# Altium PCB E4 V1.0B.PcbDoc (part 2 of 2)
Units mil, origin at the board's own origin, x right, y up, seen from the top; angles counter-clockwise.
Board outline 3543.31 x 2637.8 mil, 2 copper layers (Top Layer, Bottom Layer), stack 77.559 mil thick; 151 components, 120 nets, 552 pads, 470 vias.
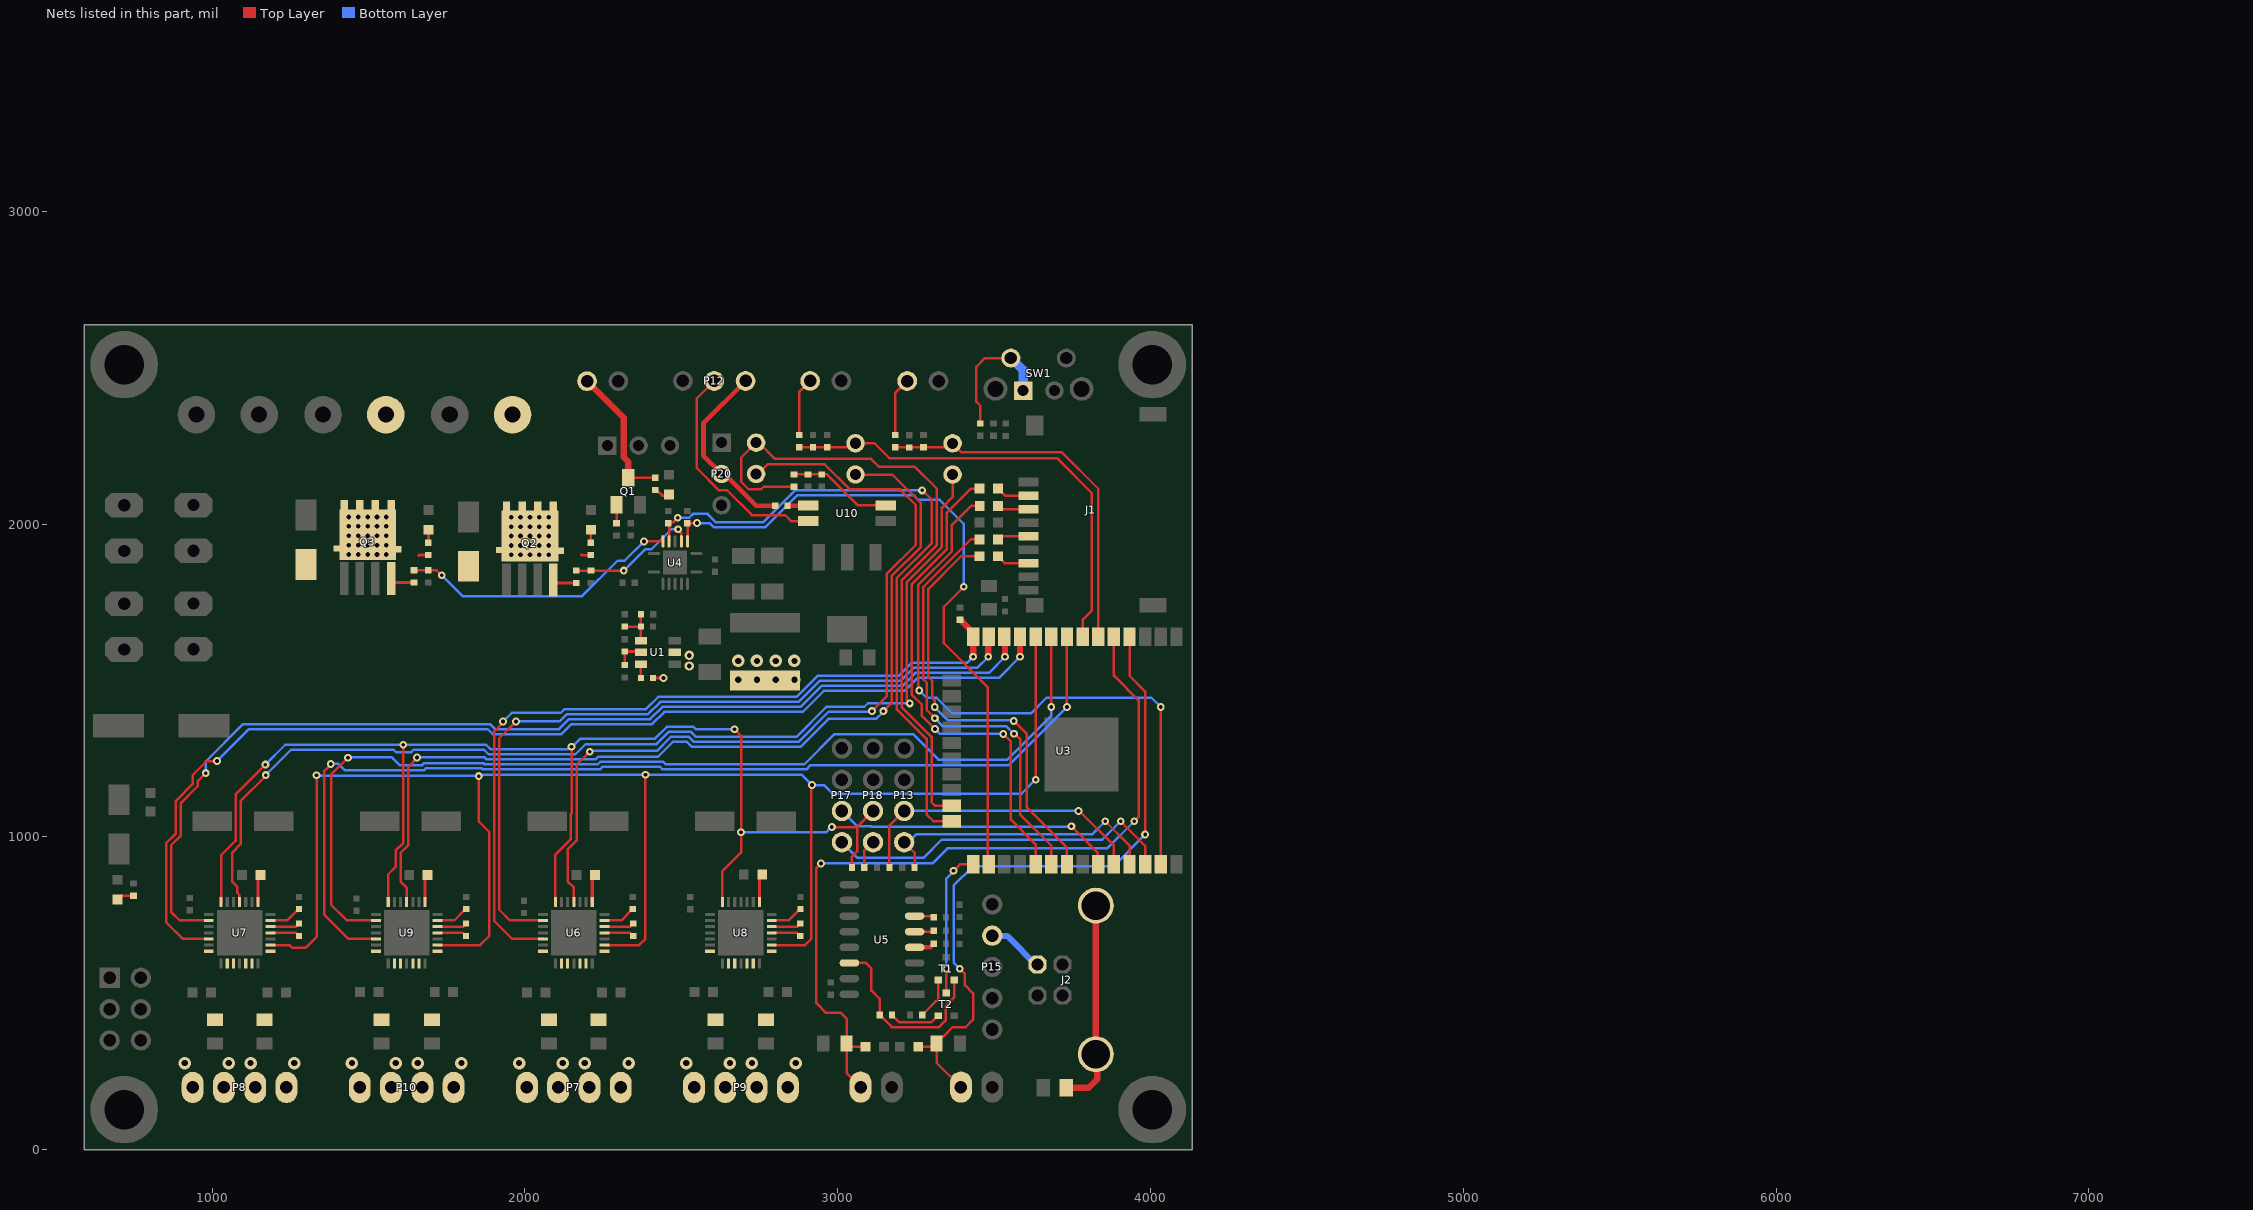
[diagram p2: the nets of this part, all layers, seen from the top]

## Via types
v1: diameter 30, hole 15, Top Layer to Bottom Layer, tented both sides, 177 vias
v2: diameter 40, hole 20, Top Layer to Bottom Layer, tented both sides, 114 vias
v3: diameter 25, hole 12, Top Layer to Bottom Layer, tented both sides, 109 vias
v4: diameter 35, hole 20, Top Layer to Bottom Layer, 36 vias
v5: diameter 40, hole 20, Top Layer to Bottom Layer, 16 vias
v6: diameter 25, hole 15, Top Layer to Bottom Layer, tented both sides, 16 vias
v7: diameter 39.37, hole 39.37, Top Layer to Bottom Layer, 2 vias

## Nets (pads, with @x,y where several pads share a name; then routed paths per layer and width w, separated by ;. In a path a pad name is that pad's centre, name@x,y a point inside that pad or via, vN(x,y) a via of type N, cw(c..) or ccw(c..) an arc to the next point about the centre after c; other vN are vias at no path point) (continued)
HEAT_BED: R30.1 U3.26 U4.2 | length 2205.3
  Top Layer w8: R30.1@2517.33,2004.26 2519.8,2001.78 U4.2@2519.8,1944.82 ; R30.1@2519.33,2002.84 v3@2549.31,2002.84 ; v3(3403,1799.53) 3339,1735.53 3339,1619.63 3479.5,1479.13 3479.5,915.5 U3.26@3483,912
  Bottom Layer w8: v3(2549.83,2003.36) 2590.74,2003.36 2604.42,1989.68 2767.78,1989.68 2871.1,2093 3242,2093 3257,2078 3326,2078 3403,2001 v3(3403,1799.53)
HEAT_BED_5V: R17.2 R20.1 U4.3 | length 418.5
  Top Layer w8: R17.2@2164.5,1851.35 R20.1@2210.98,1851.34 ; R20.1@2210.98,1851.34 v3(2316.16,1851.34) ; v3@2490.83,1979.46 2500.11,1970.18 U4.3@2500.11,1944.82
  Bottom Layer w8: v3(2316.16,1851.34) 2384.18,1919.36 2403.83,1919.36 2467.83,1983.36 v3(2489.83,1983.36)
HEAT_E0: R31.1 U3.24 U4.5 | length 2163.6
  Top Layer w8: R31.1@2457.74,2002.84 2461.68,2006.78 2475.25,2006.78 v3(2488.83,2020.36) ; U4.5@2460.74,1944.82 R31.1@2460.74,2002.36 ; v3@2485.83,2023.36 v3@2488.83,2026.36 ; v3@3271,2108 3301,2078 3301,1939.76 3188.26,1827.02 3188.26,1687 3188.26,1409.02 3284,1313.27 3284,1071.96 3305.96,1050 U3.24@3364,1050
  Bottom Layer w8: v3(2488.83,2020.36) 2524.83,2020.36 2537.06,2032.6 2584.13,2032.6 2611.04,2005.68 2761.16,2005.68 2864.47,2109 3268,2109 v3@3269,2110
  other v3: 3270,2108
HEAT_E0_5V: R26.2 R28.1 U4.6 | length 902.7
  Top Layer w8: R26.2@1645.39,1852.34 R28.1@1690.79,1852.34 1691.1,1852.64 1717.83,1852.64 v3(1734.19,1836.28) ; v3(2380.58,1944.82) U4.6@2441.06,1944.82
  Bottom Layer w8: v3(1734.19,1836.28) 1800.84,1769.63 2183.07,1769.63 2296.4,1882.96 2318.72,1882.96 v3(2380.58,1944.82)
IO0: T2.3 U3.25 | length 471.3
  Top Layer w8: T2.3@3346.68,501.02 v3(3346.68,578.64) ; v3(3370.5,891.5) 3391,912 U3.25@3433,912
  Bottom Layer w8: v3(3346.68,578.64) 3346.68,865.68 3370.5,889.5 v3(3370.5,891.5)
M-RX: P18.2 R33.2 U6.14 U7.14 U8.14 U9.14 | length 4269.8
  Top Layer w8: U7.14@1028.55,791.89 1028.55,941.29 1074.97,987.71 1074.97,1135.97 v3(1170,1231) ; U9.14@1562.89,791.89 1562.89,880.69 1586.19,904 1586.19,955.97 1611.06,980.84 1611.06,1294.41 v3(1610.95,1294.52) ; U6.14@2097.22,791.89 2097.22,943.49 2146.84,993.11 2146.84,1073.95 2149,1076.1 v3(2149,1288) ; U8.14@2631.55,791.89 2631.55,890.63 2691,950.08 v3(2691,1014.71) 2691,1323.41 v3(2670.16,1344.25) ; v3@2979.33,1031.56 v3(2981.33,1031.56) 3059.71,1031.56 ; R33.2@3045.31,902.16 3045.31,936.84 3063,954.53 3063,1032.85 P18.2@3113,1082.85
  Bottom Layer w8: v3(1170,1231) 1233.52,1294.52 v3(1610.95,1294.52) 1875.9,1294.52 1890.92,1279.5 2135.9,1279.5 2142.4,1286 v3@2152,1286 ; v3@2152,1289 2177,1314 2415.33,1314 2453.33,1352 2538.9,1352 2546.65,1344.25 v3(2670.16,1344.25) ; v3(2691,1014.71) 2962.47,1014.71 v3@2977.32,1029.56
M-TX: P18.1 R33.1 | length 92.4
  Top Layer w8: R33.1@3084.68,902.16 3084.68,954.53 P18.1@3113,982.85
MISO: L5.1 U3.31 | length 1393.5
  Top Layer w8: v3(3310.01,1415.08) 3310,1436.68 3301.51,1445.16 3301.51,1499.17 3290.26,1510.42 3290.26,1793.26 3394.37,1897.37 L5.1@3453.47,1897.37 ; v3(3562.76,1370.25) 3564.01,1370.25 3604.21,1330.05 3604.21,1095.16 3733,966.37 U3.31@3733,912
  Bottom Layer w8: v3(3310.01,1415.08) 3352.59,1372.5 3560.51,1372.5 v3(3562.76,1370.25)
MOSI: L3.1 U3.37 | length 2027.4
  Top Layer w8: v3(3260.76,1468.42) 3258.26,1470.92 3258.26,1806.51 3365,1913.25 3365,1997.31 3426.2,2058.51 L3.1@3453.94,2058.51 ; U3.37@4033,912 v3(4033,1414.95)
  Bottom Layer w8: v3(3260.76,1468.42) 3284.18,1445 3316.1,1445 3366.35,1394.75 3617.76,1394.75 3668.01,1445 4002.95,1445 v3(4033,1414.95)
MOTOR_EN: U3.10 U6.2 U7.2 U8.2 U9.2 | length 5479.8
  Top Layer w8: U7.2@1186.14,653.99 1247.38,653.99 1255.96,645.41 1298.84,645.41 1333.67,680.25 v3(1333.67,1197) ; U9.2@1720.48,653.99 1856.7,653.99 1885.97,683.25 1885.97,1015.37 1852.24,1049.1 v3(1852.24,1194.24) ; U6.2@2254.81,653.99 2365.22,653.99 2385.23,674 2385.23,1198.55 v3(2385.3,1198.62) ; U8.2@2789.14,653.99 2895.54,653.99 2915.97,674.42 2915.97,1164.28 v3(2917.61,1165.92) ; v3(3633,1182.85) 3633,1633.46 3629.73,1636.73 U3.10@3633,1640
  Bottom Layer w8: v3(1333.67,1197) 1335.05,1195.62 1850.86,1195.62 v3(1852.24,1194.24) ; v3@1852.78,1197.49 1864.97,1197.49 1865.51,1198.03 2384.71,1198.03 v3(2385.3,1198.62) ; v3@2384.92,1199 2884.52,1199 v3(2917.61,1165.92) 2955.66,1165.92 2983.2,1138.37 3588.52,1138.37 v3(3633,1182.85)
NetC1_1: C1.1 U1.6 | length 44.5
  Top Layer w8: C1.1@2370.57,1507.99 2370.57,1552.13 U1.6@2370.8,1552.36
NetC1_2: C1.2 L1.1 U1.2 | length 32.7
  Top Layer w10: C1.2@2409.94,1507.99 v3(2442.68,1507.99)
  other v1: 2525.26,1546.26 2525.26,1580.26
  other v2: 2681.68,1502.77 2741.68,1502.77 2801.68,1502.77 2861.68,1502.77 2681.68,1562.77 2741.68,1562.77 2801.68,1562.77 2861.68,1562.77
NetC4_2: C4.2 R4.2 R9.1 U1.4 | length 136.1
  Top Layer w8: R9.1@2319.5,1672.27 C4.2@2370.57,1672.27 ; R4.2@2370.65,1712.15 2370.65,1627.32 U1.4@2370.8,1627.16
NetC15_1: C15.1 U6.8 | length 73.3
  Top Layer w10: U6.8@2215.33,791.89 C15.1@2215.33,865.21
NetC18_1: C18.1 R27.2 R29.1 U10.4 | length 334.9
  Top Layer w8: R29.1@2860.1,2159.02 C18.1@2948.92,2159.02 2966.38,2159.02 3065.4,2060 U10.4@3154.02,2060
NetC21_2: C21.2 U5.4 | length 66.1
  Top Layer w15: U5.4@3245.94,646.89 3295.99,646.89 C21.2@3307.32,658.21
NetC24_1: C24.1 U7.8 | length 73.3
  Top Layer w10: U7.8@1146.66,791.89 C24.1@1146.66,865.21
NetC34_1: C34.1 U8.8 | length 73.3
  Top Layer w10: U8.8@2749.66,791.89 C34.1@2749.66,865.21
NetC36_1: C36.1 U9.8 | length 73.3
  Top Layer w10: U9.8@1681,791.89 C36.1@1681,865.21
NetC42_2: C42.2 U6.6 | length 104.7
  Top Layer w8: U6.6@2254.81,732.73 2308.26,732.73 C42.2@2344.5,768.97
NetC43_1: C43.1 U6.5 | length 95.2
  Top Layer w8: U6.5@2254.81,713.04 2336.48,713.04 C43.1@2346.06,722.63
NetC43_2: C43.2 U6.4 | length 95.4
  Top Layer w8: U6.4@2254.81,693.36 2335.96,693.36 C43.2@2346.06,683.26
NetC44_2: C44.2 U7.6 | length 104.7
  Top Layer w8: U7.6@1186.14,732.73 1239.6,732.73 C44.2@1275.83,768.97
NetC45_1: C45.1 U7.5 | length 95.2
  Top Layer w8: U7.5@1186.14,713.04 1267.81,713.04 C45.1@1277.4,722.63
NetC45_2: C45.2 U7.4 | length 95.4
  Top Layer w8: U7.4@1186.14,693.36 1267.29,693.36 C45.2@1277.4,683.26
NetC72_2: C72.2 U8.6 | length 104.7
  Top Layer w8: U8.6@2789.14,732.73 2842.6,732.73 C72.2@2878.83,768.97
NetC73_1: C73.1 U8.5 | length 95.2
  Top Layer w8: U8.5@2789.14,713.04 2870.81,713.04 C73.1@2880.4,722.63
NetC73_2: C73.2 U8.4 | length 95.4
  Top Layer w8: U8.4@2789.14,693.36 2870.29,693.36 C73.2@2880.4,683.26
NetC74_2: C74.2 U9.6 | length 104.7
  Top Layer w8: U9.6@1720.48,732.73 1773.93,732.73 C74.2@1810.17,768.97
NetC75_1: C75.1 U9.5 | length 95.2
  Top Layer w8: U9.5@1720.48,713.04 1802.15,713.04 C75.1@1811.73,722.63
NetC75_2: C75.2 U9.4 | length 95.4
  Top Layer w8: U9.4@1720.48,693.36 1801.63,693.36 C75.2@1811.73,683.26
NetD2_1: D2.1 R7.2 | length 47.8
  Top Layer w8: R7.2@2424.23,2105.98 2439.27,2090.94 D2.1@2465.76,2090.94
NetD4_2: D4.2 R2.2 | length 56.3
  Top Layer w8: D4.2@696.8,799.94 708.61,811.76 R2.2@748.26,811.76
NetD6_1: D6.1 R16.2 | length 41.3
  Top Layer w8: R16.2@2210.93,1940.65 2210.93,1981.72 D6.1@2211.08,1981.87
NetD7_1: D7.1 P4.2 Q2.5 Q2.6 Q2.7 Q2.8 R16.1 | length 31.3
  Top Layer w8: 2180.25,1902.76 2181.73,1901.28 R16.1@2210.93,1901.28
  other v1: 1956.09,1901.78 1986.09,1901.78 2016.09,1901.78 2046.09,1901.78 2076.09,1901.78 1956.09,1931.78 1986.09,1931.78 2016.09,1931.78 2046.09,1931.78 2076.09,1931.78 1956.09,1961.78 1986.09,1961.78 2016.09,1961.78 2046.09,1961.78 2076.09,1961.78 1956.09,1991.78 1986.09,1991.78 2016.09,1991.78 2046.09,1991.78 2076.09,1991.78 1956.09,2021.78 1986.09,2021.78 2016.09,2021.78 2046.09,2021.78 2076.09,2021.78
NetD8_1: D8.1 R25.2 | length 41.2
  Top Layer w10: R25.2@1691.25,1940.65 D8.1@1691.25,1981.87
NetD9_1: D9.1 P11.2 Q3.5 Q3.6 Q3.7 Q3.8 R25.1 | length 31.9
  Top Layer w10: 1659.98,1899.76 1661.5,1901.28 R25.1@1691.25,1901.28
  other v1: 1436.98,1902.76 1466.98,1902.76 1496.98,1902.76 1526.98,1902.76 1556.98,1902.76 1436.98,1932.76 1466.98,1932.76 1496.98,1932.76 1526.98,1932.76 1556.98,1932.76 1436.98,1962.76 1466.98,1962.76 1496.98,1962.76 1526.98,1962.76 1556.98,1962.76 1436.98,1992.76 1466.98,1992.76 1496.98,1992.76 1526.98,1992.76 1556.98,1992.76 1436.98,2022.76 1466.98,2022.76 1496.98,2022.76 1526.98,2022.76 1556.98,2022.76
NetEXT-RST_1: EXT-RST.1 R21.1 SW1.1 | length 428.9
  Top Layer w8: R21.1@3455.75,2321.74 3455.75,2379.25 3443,2392 3443,2502.5 3471.5,2531 SW1.1@3553.75,2531
  Bottom Layer w30: SW1.1@3553.75,2531 3593,2491.75 EXT-RST.1@3593,2427
NetJ1_2: J1.2 L2.2 | length 106.8
  Top Layer w8: L2.2@3512.53,2113.69 3534.97,2091.25 J1.2@3610.05,2091.25
NetJ1_3: J1.3 L3.2 | length 101.4
  Top Layer w8: L3.2@3513,2058.51 3523.56,2047.95 J1.3@3610.05,2047.95
NetJ1_5: J1.5 L4.2 | length 101.8
  Top Layer w8: L4.2@3512.53,1951.11 3522.75,1961.33 J1.5@3610.05,1961.33
NetJ1_7: J1.7 L5.2 | length 106.9
  Top Layer w8: L5.2@3512.53,1897.37 3535.19,1874.72 J1.7@3610.05,1874.72
NetJ2_S1: J2.S1 J2.S2 L7.1 | length 654.8
  Top Layer w20: L7.1@3731.4,198 3803,198 3830,225 J2.S1@3830,295 ; J2.S1@3825.21,305.33 J2.S2@3825.21,780.34
NetP2_1: P2.1 Q1.3 R7.1 | length 449.5
  Top Layer w8: Q1.3@2330.22,2148.47 R7.1@2416.69,2148.47
  Top Layer w20: P2.1@2198.68,2457 2316.16,2339.53 2316.16,2213.44 2330.22,2199.37 Q1.3@2330.22,2148.47
NetP5_1: P5.1 R19.1 | length 188.1
  Top Layer w8: R19.1@3183.81,2285.39 3183.81,2419.07 P5.1@3222.32,2457.57
NetP6_1: P6.1 R24.1 | length 187.1
  Top Layer w8: R24.1@2876.73,2285.27 2876.73,2422.7 P6.1@2911.86,2457.83
NetP7_1: P7.1 U6.1
  other v5: 2331.27,277
NetP7_2: P7.2 U6.26
  other v5: 2191.27,277
NetP7_3: P7.3 U6.24
  other v5: 2121.27,277
NetP7_4: P7.4 U6.21
  other v5: 1981.27,277
NetP8_1: P8.1 U7.1
  other v5: 1262.61,277
NetP8_2: P8.2 U7.26
  other v5: 1122.61,277
NetP8_3: P8.3 U7.24
  other v5: 1052.61,277
NetP8_4: P8.4 U7.21
  other v5: 912.61,277
NetP9_1: P9.1 U8.1
  other v5: 2865.61,277
NetP9_2: P9.2 U8.26
  other v5: 2725.61,277
NetP9_3: P9.3 U8.24
  other v5: 2655.61,277
NetP9_4: P9.4 U8.21
  other v5: 2515.61,277
NetP10_1: P10.1 U9.1
  other v5: 1796.94,277
NetP10_2: P10.2 U9.26
  other v5: 1656.94,277
NetP10_3: P10.3 U9.24
  other v5: 1586.94,277
NetP10_4: P10.4 U9.21
  other v5: 1446.94,277
NetP12_2: P12.2 U10.2 | length 728.3
  Top Layer w8: P12.2@2605.26,2457.65 2549.31,2401.7 2549.31,2179.37 2620.68,2108 2646.79,2108 2725.93,2028.86 2832.24,2028.86 2851.1,2010 U10.2@2905.98,2010
NetQ1_1: Q1.1 R10.1 | length 59
  Top Layer w8: R10.1@2292.82,2002.85 Q1.1@2292.82,2061.86
NetQ2_4: Q2.4 R17.1 | length 64.6
  Top Layer w10: Q2.4@2099.87,1811.98 R17.1@2164.5,1811.98
NetQ3_4: Q3.4 R26.1 | length 81.9
  Top Layer w10: Q3.4@1571.98,1826.56 1571.98,1821.75 1580.76,1812.97 R26.1@1645.39,1812.97
NetR1_1: R1.1 R8.2 U1.5 | length 96
  Top Layer w8: R8.2@2319.5,1549.26 R1.1@2319.5,1592.76 2367.8,1592.76 U1.5@2370.8,1589.76
NetR5_2: R5.2 T1.1 | length 136.3
  Top Layer w8: R5.2@3270.1,430.39 3270.1,431.18 3275.95,437.02 3276.73,437.02 3316.12,476.41 3321.09,476.41 T1.1@3321.09,542.22
NetR6_1: R6.1 T2.1 | length 165.6
  Top Layer w8: R6.1@3173.8,430.39 3173.8,429.6 3179.64,423.76 3180.43,423.76 3196.43,407.76 3299.69,407.76 3320.11,428.18 T2.1@3321.09,428.18
NetR13_1: R13.1 U10.1 | length 66.9
  Top Layer w15: R13.1@2839.68,2058.51 2904.49,2058.51 U10.1@2905.98,2060
NetR65_2: R65.2 U6.27
NetR66_2: R66.2 U7.27
NetR67_2: R67.2 U6.23
NetR68_2: R68.2 U7.23
NetR73_2: R73.2 U8.27
NetR74_2: R74.2 U9.27
NetR75_2: R75.2 U8.23
NetR76_2: R76.2 U9.23
RTS: R6.2 T1.2 U5.14 | length 614.3
  Top Layer w8: U5.14@3037.28,596.89 3090.11,596.89 3107.65,579.34 3107.65,508.89 3134.43,482.12 R6.2@3134.43,430.39 3134.43,429.6 3140.27,423.76 3141.06,423.76 3173.06,391.76 3324.28,391.76 3344.91,412.38 3344.91,459.63 3370.5,485.22 3370.5,486.32 3372.28,488.1 T1.2@3372.28,542.22
RXD0: P13.2 R35.2 U3.34 | length 976.7
  Top Layer w8: R35.2@3165.34,902.16 3165.34,1035.81 P13.2@3212.38,1082.85 ; v3@3768,1082.85 3772.17,1082.85 3883,972.03 U3.34@3883,912
  Bottom Layer w8: P13.2@3212.38,1082.85 v3@3768,1082.85
  other v3: 3770.09,1082.85
SCK: L4.1 U3.30 | length 1421.2
  Top Layer w8: v3(3310.6,1379.6) 3285.26,1404.94 3285.26,1492.8 3274.26,1503.8 3274.26,1799.88 3425.48,1951.11 L4.1@3453.47,1951.11 ; v3@3563.74,1332.85 3583,1313.6 3583,1071.58 3683,971.58 U3.30@3683,912
  Bottom Layer w8: v3(3310.6,1379.6) 3336.84,1353.35 3539.41,1353.35 3562.91,1329.85 v3(3563.74,1329.85)
SCL: P17.1 U3.36 | length 1130.8
  Top Layer w8: v3(3904.74,1050) 3983,971.74 U3.36@3983,912
  Bottom Layer w8: P17.1@3013.62,982.85 3063.62,932.85 3274.26,932.85 3332.25,990.84 3845.58,990.84 v3(3904.74,1050)
SDA: P17.2 U3.33 | length 911.8
  Top Layer w8: v3(3747,1034.08) 3832.21,948.86 3832.21,912.79 U3.33@3833,912
  Bottom Layer w8: P17.2@3013.62,1082.85 3063,1033.47 3107.03,1033.47 3107.65,1032.85 v3@3747,1032.85
SS: L2.1 U3.29 | length 1590.9
  Top Layer w8: v3(3310.82,1344.69) 3268,1387.51 3268,1424 3236.26,1455.74 3236.26,1807.14 3349,1919.88 3349,2036.97 3425.72,2113.69 L2.1@3453.47,2113.69 ; v3(3529.26,1328.85) 3553.75,1304.36 3553.75,1054.96 3633,975.71 U3.29@3633,912
  Bottom Layer w8: v3(3310.82,1344.69) 3325.5,1330.01 3528.11,1330.01 v3(3529.26,1328.85)
TB: C10.2 P3.1 R12.1 U3.5 | length 2557.8
  Top Layer w8: v3(2946.83,915.34) 2931.97,900.48 2931.97,468.39 2962.8,437.56 3009.87,437.56 3028.28,419.15 C10.2@3028.28,339.73 ; P3.1@3073,200 3028.28,244.72 C10.2@3028.28,339.73 ; R12.1@3089.04,329.26 3038.75,329.26 C10.2@3028.28,339.73 ; U3.5@3883,1640 3883,1515.68 3962,1436.68 3962,1064 v3(3948,1050)
  Bottom Layer w8: v3(2946.83,915.34) 3303.34,915.34 3351,963 ; 3351,963.56 3861.56,963.56 v3(3948,1050)
TE: C7.2 P1.1 R3.1 U3.4 | length 2189.3
  Top Layer w8: R3.1@3257.43,329.26 C7.2@3305.58,329.26 ; v3(3389.99,578.64) 3406.36,562.27 3406.36,526.16 3433,499.52 3433,415.68 3408.67,391.35 3367.67,391.35 3337.64,361.32 3331.73,361.32 3305.58,335.17 C7.2@3305.58,329.26 ; P1.1@3394,200 3316.05,277.95 C7.2@3316.05,339.73 C7.2@3305.58,329.26 ; U3.4@3933,1640 3933,1515.17 3983,1465.17 v3(3983,1007.72)
  Bottom Layer w8: v3(3389.99,578.64) 3370.5,598.13 3370.5,844.31 3432.19,906 3881.28,906 v3(3983,1007.72)
TXD0: P13.1 R34.2 U3.35 | length 935.6
  Top Layer w8: P13.1@3212.38,982.85 3245.94,949.29 R34.2@3245.94,902.16 ; v3(3855.53,1050) 3933,972.53 U3.35@3933,912
  Bottom Layer w8: P13.1@3212.38,982.85 3225.55,982.85 3250.42,1007.72 3813.25,1007.72 v3(3855.53,1050)
UD+: R37.2 U5.5 | length 62.5
  Top Layer w8: U5.5@3245.94,696.89 3304.64,696.89 R37.2@3307.32,699.56
UD-: R36.2 U5.6 | length 63.2
  Top Layer w8: U5.6@3245.94,746.89 3302.99,746.89 R36.2@3307.32,742.56
UVCC: J2.1 P15.2 | length 187.1
  Bottom Layer w20: P15.2@3494,684.26 3494.81,683.45 3541.55,683.45 J2.1@3640,585
X-DIAG: JP1.1 U7.11 | length 3439.6
  Top Layer w8: U7.11@1087.61,791.11 1086.69,792.03 1086.69,814.99 1079.41,822.27 1079.41,840.9 1064.41,855.9 1064.41,950.07 1090.97,976.64 1090.97,1114.92 v3@1171.39,1195.33 ; v3@3233.26,1424.19 3220.26,1437.19 3220.26,1813.77 3333,1926.51 3333,2052.01 3367.4,2086.41 JP1.1@3367.4,2158.42
  Bottom Layer w8: v3(1171.39,1197.49) 1252.42,1278.52 1580,1278.52 1588.5,1270.02 1635.62,1270.02 1644.12,1278.52 1869.27,1278.52 1884.3,1263.5 2160.97,1263.5 2194.47,1297 2420.95,1297 2459.45,1335.5 2531.03,1335.5 2546.78,1319.75 2867.75,1319.75 2964,1416 3085,1416 3096,1427 v3@3224.66,1427
  other v3: 3230.26,1427
X_DIR: U3.11 U7.19 | length 3543
  Top Layer w8: U7.19@989.07,673.67 906.56,673.67 853,727.23 853,979.81 884,1010.81 884,1115.25 937.22,1168.48 937.22,1197.19 982.6,1242.57 v3(1015.43,1242.57)
  Top Layer w20: v3(3583,1576) U3.11@3583,1640
  Bottom Layer w8: v3(1015.43,1242.57) 1117.36,1344.5 1881.08,1344.5 1897.08,1328.5 2116.5,1328.5 2148.43,1360.43 2406.6,1360.43 2446.02,1399.85 2888.22,1399.85 2955.37,1467 3213.88,1467 3255.31,1508.43 3515.43,1508.43 v3(3583,1576)
X_MIN: C14.1 JP1.2 R18.2 R19.2 U3.6 | length 1187.6
  Top Layer w8: R19.2@3183.81,2246.02 3228.84,2246.02 R18.2@3274.26,2246.02 3341.19,2246.02 3353.58,2258.42 JP1.2@3367.4,2258.42 3396.4,2229.41 3716.59,2229.41 3833,2113 U3.6@3833,1640
X_STEP: U3.12 U7.16 | length 3430.7
  Top Layer w8: v3(979.41,1203.8) 953.22,1177.61 953.22,1161.85 900,1108.63 900,1004.19 869,973.19 869,760.1 896.37,732.73 U7.16@989.07,732.73 ; U3.12@3533,1640 U3.12@3534.97,1638.03
  Top Layer w20: v3(3534.97,1576) U3.12@3534.97,1638.03
  Bottom Layer w8: v3(979.41,1203.8) 979.41,1241.43 1098.48,1360.5 1887.7,1360.5 1903.7,1344.5 2109.5,1344.5 2141.43,1376.43 2399.97,1376.43 2439.4,1415.85 2881.6,1415.85 2948.75,1483 3207.25,1483 3248.68,1524.43 3483.4,1524.43 v3(3534.97,1576)
Y-DIAG: JP2.1 U9.11 | length 3022.1
  Top Layer w8: U9.11@1621.94,791.89 1621.94,838.12 1602.19,857.87 1602.19,949.34 1627.06,974.21 1627.06,1224.11 1655.54,1252.59 1659.31,1252.59 v3@1660.74,1254.02 ; JP2.1@3056.86,2158.67 3174.33,2158.67 3266,2067 3266,1927.39 3172.26,1833.65 3172.26,1428.26 v3@3147,1403
  Bottom Layer w8: v3@1660.74,1254.02 1661.64,1254.92 1870.25,1254.92 1877.67,1247.5 2226.25,1247.5 2235.75,1257 2426.21,1257 2472.71,1303.5 2517.78,1303.5 2533.53,1287.75 2881,1287.75 2970.25,1377 3123,1377 v3@3146,1400
  other v3: 1654.74,1254.02 3145.97,1402.03
Y_DIR: U3.8 U9.19 | length 3365.8
  Top Layer w8: v3@1380,1232 1359.04,1211.04 1359.04,750.6 1435.96,673.67 U9.19@1523.41,673.67 ; v3(3733,1414.95) U3.8@3733,1640
  Bottom Layer w8: v3(1379.04,1233.22) 1403.78,1233.22 1423.48,1213.52 1677.52,1213.52 1682.73,1218.74 1861.17,1218.74 1864.41,1215.5 2239.5,1215.5 2247.5,1223.5 2432.5,1223.5 2440,1216 2899.76,1216 2913.26,1229.5 3547.55,1229.5 v3(3733,1414.95)
Y_MIN: C17.1 JP2.2 R23.2 R24.2 U3.7 | length 1478.9
  Top Layer w8: R24.2@2876.73,2245.9 3030.27,2245.9 3043.04,2258.67 JP2.2@3056.86,2258.67 3117.14,2258.67 3164.81,2211 3700.63,2211 3813,2098.63 3813,1723.64 3783,1693.64 U3.7@3783,1640
Y_STEP: U3.9 U9.16 | length 3310
  Top Layer w8: v3(1434.12,1253.17) 1380.34,1199.39 1380.34,782.99 1430.6,732.73 U9.16@1523.41,732.73 ; v3(3683,1414.95) U3.9@3683,1640
  Bottom Layer w8: v3(1434.12,1253.17) 1434.97,1254.02 1574.63,1254.02 1599.13,1229.52 1670.89,1229.52 1676.1,1234.74 1867.8,1234.74 1871.04,1231.5 2232.87,1231.5 2240.87,1239.5 2442.64,1239.5 2450.14,1232 2893.14,1232 2989.83,1328.69 3240.48,1328.69 3321.89,1247.28 3542.7,1247.28 3683,1387.58 v3(3683,1414.95)
Z-DIAG: JP3.1 U6.11 | length 2768.2
  Top Layer w8: U6.11@2156.27,791.89 2156.27,838.27 2136.67,857.87 2136.67,960.31 2165,988.64 2165,1230.61 2209.39,1275 v3@2211.08,1275 ; JP3.1@2745.26,2160.42 2776.04,2191.2 2958.47,2191.2 3038.66,2111 3199.37,2111 3250,2060.37 3250,1934.02 3156.26,1840.28 3156.26,1449.26 v3@3110,1403
  Bottom Layer w8: v3@2211.08,1275 2421.58,1275 2466.08,1319.5 2524.4,1319.5 2540.15,1303.75 2874.38,1303.75 2970.63,1400 3102.01,1400 v3@3103.65,1401.65
  other v3: 2207.08,1272 3109.86,1402.03
Z-VCC: P12.1 P20.2 R13.2 | length 584.8
  Top Layer w15: P20.2@2628.7,2160.42 2570.76,2218.36 2570.76,2323.15 P12.1@2705.26,2457.65 ; P20.2@2634.7,2160.42 2637.03,2160.42 2738.94,2058.51 R13.2@2800.32,2058.51
Z_DIR: R22.2 U3.14 U6.19 | length 2558.7
  Top Layer w8: v3(1930,1369) 1933.56,1369 1901.97,1337.41 1901.97,731.17 1959.46,673.67 U6.19@2057.74,673.67
  Top Layer w20: R22.2@3391.21,1694.16 3392,1694.16 3397.84,1688.31 3397.84,1687.53 3433,1652.37 U3.14@3433,1640 v3(3433,1576)
  Bottom Layer w8: v3(1930,1369) 1957.97,1396.97 2114.97,1396.97 2126.43,1408.43 2386.72,1408.43 2426.14,1447.85 2868.34,1447.85 2935.49,1515 3194,1515 3235.43,1556.43 3413.43,1556.43 v3(3433,1576)
Z_MIN: JP3.2 R29.2 U3.23 | length 2122.7
  Top Layer w8: JP3.2@2739.26,2258.49 2749.93,2258.49 2800.08,2208.35 3106.86,2208.35 3131.21,2184 3246,2184 3317,2113 3317,1933.14 3204.26,1820.39 3204.26,1415.64 3300,1319.9 3300,1110.82 3310.82,1100 U3.23@3364,1100 ; JP3.2@2739.26,2260.42 2691,2212.16 2691,2135.57 2715.57,2111 2754.85,2111 2763.5,2119.65 R29.2@2860.1,2119.65
Z_STEP: U3.13 U6.16 | length 2432.1
  Top Layer w8: v3@1966.97,1364.43 1917.97,1315.43 1917.97,767.02 1952.26,732.73 U6.16@2057.74,732.73 ; U3.13@3481.47,1638.47 U3.13@3483,1640
  Top Layer w20: v3(3481.47,1576) U3.13@3481.47,1638.47
  Bottom Layer w8: v3(1971.43,1369) 2111,1369 2134.43,1392.43 2393.35,1392.43 2432.77,1431.85 2874.97,1431.85 2942.12,1499 3200.63,1499 3242.06,1540.43 3445.89,1540.43 v3(3481.47,1576)
pads on no net: J1.1 J1.8 J1.9 SW1.3 SW1.4 U3.17 U3.18 U3.19 U3.20 U3.21 U3.22 U3.32 U3.39 U4.11 U4.12 U5.7 U5.8 U5.9 U5.10 U5.11 U5.12 U5.15 U6.7 U6.12 U6.17 U6.20 U7.7 U7.12 U7.17 U7.20 U8.7 U8.11 U8.12 U8.17 U8.20 U9.7 U9.12 U9.17 U9.20
copper on no net:
  other v7: 4023.43,1851.09 4023.43,2166.06

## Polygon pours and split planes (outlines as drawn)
GND on Top Layer "NONET_L-01_P-001" (solid, remove dead copper, pour order 0): 590.55,2637.8 590.55,0 4133.86,0 4133.86,2637.8
GND on Bottom Layer "NONET_L-01_P-001" (solid, remove dead copper, pour order 1): 590.55,2637.8 590.55,0 4133.86,0 4133.86,2637.8

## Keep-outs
Keep-Out Layer:
  lines w8: 590.55,2637.8 4133.86,2637.8 4133.86,0 590.55,0 590.55,2637.8 ; 590.55,2637.8 590.55,2637.8

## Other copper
Top Layer:
  rectangle net NetC1_2: 2650.74,1465.41 2884.74,1597.41
  region net GND: 1070,2437 1069.35,2436.35 1069.35,2261.54 1198.52,2261.54 1220.13,2283.16 1219.56,2283.72 1219.56,2435.1
  region net NetP9_3: 2653.98,313.98 2592,252 2592,163 2609,146 2666,146 2686,166 2685.98,272 2685.98,558.1 2676.61,567.47 2676.61,610.94 2665.61,610.94 2665.61,570.36 2653.98,524.9
  region net NetP9_4: 2515.61,318.29 2581,252.89 2581,163 2564.2,146.2 2496.8,146.2 2479.98,163.02 2479.98,318.29 2479.98,572.86 2546.47,639.36 2588.61,639.36 2588.61,629.36 2566.17,629.36 2515.61,558.45
  region net NetP9_1: 2865.61,318.29 2800.22,252.89 2800.22,163 2817.02,146.2 2884.41,146.2 2901.24,163.02 2901.24,318.29 2901.24,572.86 2834.74,639.36 2792.61,639.36 2792.61,629.36 2815.05,629.36 2865.61,558.45
  region net NetP9_2: 2727.24,313.98 2789.22,252 2789.22,163 2772.22,146 2715.22,146 2695.22,166 2695.24,272 2695.24,558.1 2704.61,567.47 2704.61,610.94 2715.61,610.94 2715.61,570.36 2727.24,524.9
  region net NetP7_3: 2119.65,313.98 2057.67,252 2057.67,163 2074.67,146 2131.67,146 2151.67,166 2151.64,272 2151.64,558.1 2142.27,567.47 2142.27,610.94 2131.27,610.94 2131.27,570.36 2119.65,524.9
  region net NetP7_4: 1981.27,318.29 2046.67,252.89 2046.67,163 2029.86,146.2 1962.47,146.2 1945.64,163.02 1945.64,318.29 1945.64,572.86 2012.14,639.36 2054.27,639.36 2054.27,629.36 2031.83,629.36 1981.27,558.45
  region net NetP7_1: 2331.27,318.29 2265.88,252.89 2265.88,163 2282.69,146.2 2350.08,146.2 2366.9,163.02 2366.9,318.29 2366.9,572.86 2300.41,639.36 2258.27,639.36 2258.28,629.36 2280.72,629.36 2331.28,558.45
  region net NetP7_2: 2192.9,313.98 2254.88,252 2254.88,163 2237.88,146 2180.88,146 2160.88,166 2160.9,272 2160.9,558.1 2170.27,567.47 2170.27,610.94 2181.27,610.94 2181.27,570.36 2192.9,524.9
  region net NetP10_3: 1585.31,313.98 1523.33,252 1523.33,163 1540.33,146 1597.33,146 1617.33,166 1617.31,272 1617.31,558.1 1607.94,567.47 1607.94,610.94 1596.94,610.94 1596.94,570.36 1585.31,524.9
  region net NetP10_4: 1446.94,318.29 1512.33,252.89 1512.33,163 1495.53,146.2 1428.14,146.2 1411.31,163.02 1411.31,318.29 1411.31,572.86 1477.81,639.36 1519.94,639.36 1519.94,629.36 1497.5,629.36 1446.94,558.45
  region net NetP10_1: 1796.94,318.29 1731.55,252.89 1731.55,163 1748.35,146.2 1815.75,146.2 1832.57,163.02 1832.57,318.29 1832.57,572.86 1766.08,639.36 1723.94,639.36 1723.94,629.36 1746.38,629.36 1796.94,558.45
  region net NetP10_2: 1658.57,313.98 1720.55,252 1720.55,163 1703.55,146 1646.55,146 1626.55,166 1626.57,272 1626.57,558.1 1635.94,567.47 1635.94,610.94 1646.94,610.94 1646.94,570.36 1658.57,524.9
  region net NetP8_2: 1124.24,313.98 1186.22,252 1186.22,163 1169.22,146 1112.22,146 1092.22,166 1092.24,272 1092.24,558.1 1101.61,567.47 1101.61,610.94 1112.61,610.94 1112.61,570.36 1124.24,524.9
  region net NetP8_1: 1262.61,318.29 1197.22,252.89 1197.22,163 1214.02,146.2 1281.41,146.2 1298.24,163.02 1298.24,318.29 1298.24,572.86 1231.74,639.36 1189.61,639.36 1189.61,629.36 1212.05,629.36 1262.61,558.45
  region net +24VMOT: 650.94,1833.19 612.59,1794.84 612.59,1095.09 655.73,1051.96 728.2,1051.96 787.25,1111 819,1111 832,1124 832,1331.24 832,1807.79 807.16,1832.64
  region net +3.3V: 3001.02,1941.36 3001.03,1841.38 2913.55,1753.91 2913.55,1659.88 2965.69,1607.73 2965.69,1573.93 3023.76,1515.86 3033.79,1515.86 3064.7,1546.76 3064.7,1638.47 3094.59,1668.36 3094.59,1810.14 3060.72,1844.02 3060.72,1941.36
  region net +5V: 2891.05,1760.92 2959.45,1829.32 2959.45,1855.4 2891.05,1855.4 2648.94,1855.4 2648.94,1726.35 2648.93,1620 2891.04,1620
  region net +24VMOT: 2459.68,1614.32 2624.23,1614.32 2637.68,1627.77 2637.68,1716.77 2625.68,1728.77 2472.43,1728.77 2459.68,1716.03
  region net NetC1_2: 2460.26,1577.26 2460.26,1602.26 2529.26,1602.26 2542.26,1589.26 2542.26,1533.26 2536.26,1527.26 2515.26,1527.26 2509.26,1533.26 2509.26,1569.26 2501.26,1577.26
  region net 24V2: 1734.19,1969.68 1720,1983.87 1720,2010.71 1701.05,2029.66 1701.05,2369.08 1646.85,2423 1493.76,2423 1441.76,2371 1441.76,2217.76 1352.64,2128.64 1352.64,1971.29 1228.29,1971.29 1216,1959 1216,1619 1097,1500 880.85,1500 845.57,1535.28 845.57,1809.97 880.84,1838 994,1838 1028,1872 1028,2167 1069.35,2208.35 1156.86,2208.35 1228.29,2279.78 1228.29,2542.29 1304,2618 1879.67,2618 1892.16,2605.52 1892.16,2157.81 1868,2133.65 1868,1983.17 1854.52,1969.69
  region net NetD7_1: 2114.08,2548.03 2113.98,2425.56 2218.68,2320.86 2218.69,2099.56 2187.34,2068.75 2187.34,1893.57 2168.27,1874.5 1928.09,1874.5 1869.13,1815.78 1761.03,1815.78 1761.03,1956.78 1880.7,1956.78 1881.7,1957.78 1881.7,2125.7 1905,2149 1905,2589.39 2072.72,2589.39
  region net +24V: 1015,1878.97 1015,2173.35 1050,2208.35 1050,2356.47 989.02,2417.45 882.45,2417.45 815,2350 670,2350 625,2305 625,1883 654,1854 990.03,1854
  region net +24VMOT: 2872.19,897.68 2884.62,910.12 2884.62,1129.57 2861.57,1152.62 2737.61,1152.62 2714.08,1129.08 2714.08,997.36 2825.62,885.81 2860.44,885.81
  region net +24VMOT: 1801.5,897.68 1813.93,910.12 1813.93,1129.57 1790.88,1152.62 1666.92,1152.62 1643.38,1129.08 1643.38,997.36 1754.93,885.81 1789.75,885.81
  region net +24VMOT: 2292.82,1701.97 2278.77,1716.02 2229.38,1716.03 2202.96,1689.6 2202.91,1592.81 2202.91,1381.49 2253.9,1330.5 2253.9,1203.83 2202.7,1152.62 2179.16,1129.08 2179.16,997.36 2290.71,885.81 2325.53,885.81 2337.27,897.68 2349.71,910.12 2349.71,1129.57 2326.66,1152.62 2316.16,1163.12 2316.16,1355.26 2262,1409.41 2262,1577.88 2292.82,1608.7
  region net +24VMOT: 1265.41,897.68 1277.84,910.12 1277.84,1129.57 1254.79,1152.62 1148.18,1152.62 1107.29,1111.73 1107.29,997.36 1218.84,885.81 1253.66,885.81
  region net NetP8_4: 912.61,318.29 978,252.89 978,163 961.2,146.2 893.8,146.2 876.98,163.02 876.98,318.29 876.98,572.86 943.47,639.36 985.61,639.36 985.61,629.36 963.17,629.36 912.61,558.45
  region net NetP8_3: 1050.98,313.98 989,252 989,163 1006,146 1063,146 1083,166 1082.98,272 1082.98,558.1 1073.61,567.47 1073.61,610.94 1062.61,610.94 1062.61,570.36 1050.98,524.9
  region net +24VMOT: 2803.24,519.58 2803.24,488.1 2818.24,473.1 2818.24,456.1 2807.24,445.1 2770.24,445.1 2759.24,456.1 2759.24,525.87 2744.29,570.78 2744.29,610.94 2755.29,610.94 2755.29,575.07
  region net +24VMOT: 2577.98,519.58 2577.98,488.1 2562.98,473.1 2562.98,456.1 2573.98,445.1 2610.98,445.1 2621.98,456.1 2621.98,525.87 2636.92,570.78 2636.92,610.94 2625.92,610.94 2625.92,575.07
  region net NetR73_2: 2749.8,520.54 2749.81,451.53 2788.24,413.1 2788.24,410.1 2757.24,410.1 2736.95,430.39 2736.95,522.19 2724.61,567.79 2724.61,610.94 2735.61,610.94 2735.61,567.91
  region net NetR75_2: 2631.41,520.54 2631.41,451.53 2592.98,413.1 2592.98,410.1 2623.98,410.1 2644.27,430.39 2644.27,522.19 2656.61,567.79 2656.61,610.94 2645.61,610.94 2645.61,567.91
  region net +24VMOT: 1734.57,519.58 1734.57,488.1 1749.57,473.1 1749.57,456.1 1738.57,445.1 1701.57,445.1 1690.57,456.1 1690.57,525.87 1675.63,570.78 1675.63,610.94 1686.63,610.94 1686.63,575.07
  region net +24VMOT: 1509.31,519.58 1509.31,488.1 1494.31,473.1 1494.31,456.1 1505.31,445.1 1542.31,445.1 1553.31,456.1 1553.31,525.87 1568.26,570.78 1568.26,610.94 1557.26,610.94 1557.26,575.07
  region net NetR74_2: 1681.14,520.54 1681.14,451.53 1719.57,413.1 1719.57,410.1 1688.57,410.1 1668.28,430.39 1668.28,522.19 1655.94,567.79 1655.94,610.94 1666.94,610.94 1666.94,567.91
  region net NetR76_2: 1562.74,520.54 1562.74,451.53 1524.31,413.1 1524.31,410.1 1555.31,410.1 1575.6,430.39 1575.6,522.19 1587.94,567.79 1587.94,610.94 1576.94,610.94 1576.94,567.91
  region net +24VMOT: 1200.24,519.58 1200.24,488.1 1215.24,473.1 1215.24,456.1 1204.24,445.1 1167.24,445.1 1156.24,456.1 1156.24,525.87 1141.29,570.78 1141.29,610.94 1152.29,610.94 1152.29,575.07
  region net +24VMOT: 974.98,519.58 974.98,488.1 959.98,473.1 959.98,456.1 970.98,445.1 1007.98,445.1 1018.98,456.1 1018.98,525.87 1033.92,570.78 1033.92,610.94 1022.92,610.94 1022.92,575.07
  region net NetR66_2: 1146.8,520.54 1146.81,451.53 1185.24,413.1 1185.24,410.1 1154.24,410.1 1133.95,430.39 1133.95,522.19 1121.61,567.79 1121.61,610.94 1132.61,610.94 1132.61,567.91
  region net NetR68_2: 1028.41,520.54 1028.41,451.53 989.98,413.1 989.98,410.1 1020.98,410.1 1041.27,430.39 1041.27,522.19 1053.61,567.79 1053.61,610.94 1042.61,610.94 1042.61,567.91
  region net NetR67_2: 2097.08,520.54 2097.08,451.53 2058.64,413.1 2058.64,410.1 2089.64,410.1 2109.94,430.39 2109.94,522.19 2122.27,567.79 2122.27,610.94 2111.27,610.94 2111.27,567.91
  region net NetR65_2: 2215.47,520.54 2215.47,451.53 2253.9,413.1 2253.9,410.1 2222.9,410.1 2202.61,430.39 2202.61,522.19 2190.27,567.79 2190.27,610.94 2201.27,610.94 2201.27,567.91
  region net +24VMOT: 2043.64,519.58 2043.64,488.1 2028.64,473.1 2028.64,456.1 2039.64,445.1 2076.65,445.1 2087.64,456.1 2087.64,525.87 2102.59,570.78 2102.59,610.94 2091.59,610.94 2091.59,575.07
  region net +24VMOT: 2268.9,519.58 2268.9,488.1 2283.9,473.1 2283.9,456.1 2272.9,445.1 2235.9,445.1 2224.9,456.1 2224.9,525.87 2209.96,570.78 2209.96,610.94 2220.96,610.94 2220.96,575.07
  region net NetD9_1: 1363.6,1954.76 1234.98,1954.76 1234.98,1815.76 1341.98,1815.76 1402.98,1876.76 1626.98,1876.76 1649.98,1876.76 1666.98,1893.76 1666.98,2066.76 1689.98,2089.76 1689.98,2361.76 1641.43,2410.31 1501.73,2410.32 1454.84,2363.43 1454.84,2212.63 1405.98,2163.76 1363.6,2121.38
  region: 7380.84,3477.2
  region: 2241.74,629.94
Bottom Layer:
  rectangle net GND: 1070,2243.35 1242.5,2456.89
  rectangle net NetP9_4: 2487,127.95 2581,305
  region net NetP9_3: 2685.99,305 2591.4,305 2591.4,127.95 2685.99,127.95
  rectangle net NetP9_2: 2695.23,127.95 2789.82,305
  region net NetP9_1: 2894.22,305 2800.22,305 2800.22,127.95 2894.22,127.95
  rectangle net NetP7_4: 1952.67,127.95 2046.67,305
  region net NetP7_3: 2151.66,305 2057.06,305 2057.06,127.95 2151.66,127.95
  rectangle net NetP7_2: 2160.89,127.95 2255.49,305
  region net NetP7_1: 2359.88,305 2265.88,305 2265.88,127.95 2359.88,127.95
  rectangle net NetP10_4: 1418.33,127.95 1512.33,305
  region net NetP10_3: 1617.32,305 1522.73,305 1522.73,127.95 1617.32,127.95
  rectangle net NetP10_2: 1626.56,127.95 1721.15,305
  region net NetP10_1: 1825.55,305 1731.55,305 1731.55,127.95 1825.55,127.95
  region net NetP8_1: 1291.22,305 1197.22,305 1197.22,127.95 1291.22,127.95
  rectangle net NetP8_2: 1092.23,127.95 1186.82,305
  region net NetP8_3: 1082.99,305 988.4,305 988.4,127.95 1082.99,127.95
  rectangle net NetP8_4: 884,127.95 978,305
  region net +24V: 1013.85,1879.22 1013.85,2173.61 1048.85,2208.61 1048.85,2356.73 987.87,2417.71 881.3,2417.71 813.85,2350.25 668.85,2350.25 623.85,2305.25 623.85,1883.25 652.85,1854.26 988.88,1854.25
  region net +24VMOT: 637.44,1315.44 611,1289 611,1170 725,1056 845,1056 845,1165 823,1187 823,1284.62 792.18,1315.44
  region net +24VMOT: 2229,1714 2378.9,1714 2396.36,1731.47 2546.26,1731.47 2561,1716.72 2561,1648 2546,1633 2314,1633 2278,1597 2219,1597 2205,1611 2205,1690
  region: 2462.5,1525.79
  region net NetC1_2: 2418.68,1520.78 2435.9,1538 2470.62,1538 2490.78,1558.16 2490.78,1588.57 2503.87,1602.26 2877.19,1602.26 2891.86,1587.59 2891.86,1491.74 2876.39,1476.26 2494.26,1476.26 2434.19,1476.26 2418.68,1491.77
  region net NetD7_1: 1714.09,1893.76 1820.5,1787.35 1839.77,1787.55 2176.72,1787.55 2208.09,1818.92 2208.09,2381.91 2172,2418 1924.26,2418 1892.09,2385.83 1892.09,2278.09 1859,2245 1714.09,2245
  region net NetD9_1: 1386.75,1853.64 1642.77,1853.64 1689.99,1900.85 1689.98,2361.76 1637.2,2414.55 1473.77,2414.55 1424.98,2365.76 1424.98,2182.76 1386.75,2144.53

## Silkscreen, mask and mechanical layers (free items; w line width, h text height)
Top Overlay:
  text "Y-MIN" at 3075,2615 h75 r180
  text "X-MIN" at 3378,2615 h75 r180
  text "PWR IN" at 1182.57,2614 h75 r180
  text "HEATER" at 1616.83,2614 h75 r180
  text "HOTBED" at 2025.09,2614 h75 r180
  text "+ FAN" at 2369.4,2614 h75 r180
  text "Z-MIN" at 2705.26,2614 h75 r180
  text "ZDIAG-EN" at 2800.68,2307.35 h30 r270
  text "YDIAG-EN" at 3121.89,2307.35 h30 r270
  text "24V" at 2531.28,2297.36 h30 r270
  text "24V" at 2120.3,2235.59 h30
  text "XDIAG-EN" at 3265.76,2205.41 h30 r270
  text "5V" at 2505.33,2168.74 h30 r270
  text "5V" at 2611.76,1963.52 h30
  text "V1.0" at 1777.49,1409.25 h150
  text "E4" at 1204.9,1380.73 h400
  text "BASED ON ESP32 & TMC2209" at 1212.45,1327.89 h80
  text "5V" at 2938,1263 h30 r90
  text "5V" at 3311,1258 h30 r90
  text "By fysetc.com" at 1212.45,1255 h80
  text "GND" at 2938,1152 h30 r90
  text "GND" at 3311,1149 h30 r90
  text "RXD" at 3311,1047 h30 r90
  text "SDA" at 2938,1045 h30 r90
  text "SCL" at 2938,947 h30 r90
  text "TXD" at 3311,942 h30 r90
  text "24V" at 696.8,623.08 h40 r90
  text "GND" at 795,621.63 h40 r90
  text "MOT X" at 950.11,10.98 h75
  text "MOT Y" at 1494.31,10.98 h75
  text "MOT Z" at 2053.17,10.98 h75
  text "MOT E" at 2568.48,10.98 h75
  text "TB" at 3073,10.98 h75
  text "TE" at 3394,10.98 h75
Bottom Overlay:
  lines w5.91: 1050.38,2221.22 1050.38,2265.22 ; 1455.23,2221.22 1455.23,2265.22 ; 1860.38,2221.22 1860.38,2265.22 ; 2246.79,2369.61 2246.79,2413.61 ; 2293.5,2152.01 2293.5,2196.01 ; 2430.5,2152.01 2430.5,2196.01 ; 2529.71,2120.61 2573.71,2120.61 ; 2529.71,2208.61 2573.71,2208.61 ; 2560.15,2368.26 2560.15,2412.26 ; 2650.36,2368.26 2650.36,2412.26 ; 2961.97,2368.44 2961.97,2412.44 ; 3272.43,2368.19 3272.43,2412.19 ; 3648,2328 3648,2372
  lines w7.87: 856,2226.09 856,2568 ; 1253.84,2226.09 1253.84,2568 ; 1659,2226.09 1659,2568 ; 2054,2226.09 2054,2568 ; 2950.63,1182.85 3191.89,1182.85 ; 2950.63,1282.85 3194.38,1282.85 ; 3113,860.82 3113,964.85 ; 3113,1082.85 3118.3,1082.85 3165.34,1035.81 3165.34,918.41
  text "HEATER" at 1623.12,2528.09 h75
  text "Z-MIN" at 2711.15,2528.23 h75
  text "Y-MIN" at 3080.75,2528.41 h75
  text "X-MIN" at 3391.21,2528.16 h75
  text "PWR IN" at 1189.49,2527.58 h75
  text "HOTBED" at 2027.69,2527.58 h75
  text "PRT-FAN" at 2414.58,2527.58 h75
  text "GND" at 2227.97,2375.61 h30
  text "VFAN" at 2363,2375.61 h30
  text "GND" at 2543.83,2374.61 h30
  text "SIG" at 2631.54,2374.25 h30
  text "VZ" at 2718.99,2374.28 h30
  text "SIG" at 2943.14,2374.43 h30
  text "GND" at 3059.17,2374.43 h30
  text "SIG" at 3253.6,2374.18 h30
  text "GND" at 3369.63,2374.18 h30
  text "RST" at 3629.18,2333.99 h30
  text "GND" at 3745.2,2333.99 h30
  text "24V" at 2535.7,2228.62 h30 r270
  text "24V" at 1031.56,2227.21 h30
  text "GND" at 1147.59,2227.21 h30
  text "24V" at 1436.41,2227.21 h30
  text "GND" at 1552.43,2227.21 h30
  text "24V" at 1841.56,2227.21 h30
  text "GND" at 1957.59,2227.21 h30
  text "24V" at 2273.49,2158 h30
  text "VFAN" at 2411.67,2158 h30
  text "5V" at 2495.7,2158 h30
  text "VZ" at 2535.7,2139.43 h30 r270
  text "ZDIAG-EN" at 2790,2096 h30 r270
  text "YDIAG-EN" at 3114.86,2094.95 h30 r270
  text "XDIAG-EN" at 3419.61,2094.95 h30 r270
  text "5V" at 2535.7,2055.4 h30 r270
  text "E4" at 2666.61,1467.9 h500
  text "BASED ON ESP32 & TMC2209" at 2666.61,1357.78 h80
  text "5V" at 2932.62,1265.02 h30
  text "Designed and produced" at 2666.61,1248.9 h80
  text "GND" at 2932.62,1169.64 h30
  text "in China" at 2666.61,1148.9 h80
  text "SDA" at 2957.63,1071.64 h30
  text "RXD0" at 3363.36,1067.76 h30
  text "by fysetc.com" at 2666.61,1048.9 h80
  text "SCL" at 2957.62,971.64 h30
  text "TXD0" at 3363.36,967.76 h30
  text "wiki.fysetc.com/e4/" at 2666.61,950.08 h80
  text "2209RX" at 3301.26,871.96 h30
  text "2209TX" at 3221.26,814.09 h30
  text "SYS5V" at 3428,768.42 h30
  text "USB5V" at 3428,673.05 h30
  text "DM" at 3428,573.04 h30
  text "DP" at 3428,473.05 h30
  text "GND" at 3428,373.05 h30
  text "MOT Z" at 2802.55,80.77 h75
  text "MOT X" at 2275.45,78.89 h75
  text "MOT E" at 1206.64,72.38 h75
  text "MOT Y" at 1740.08,72.38 h75
Bottom Solder:
  region: 2115.3,2060.98 1917.66,2060.98 1917.66,1863.34 2115.3,1863.34
  region: 1596.2,2061.98 1398.56,2061.98 1398.56,1864.34 1596.2,1864.34
  region: 2255.49,594.15 2255.49,791.78 2057.85,791.78 2057.85,594.15
  region: 1186.82,594.15 1186.82,791.78 989.18,791.78 989.18,594.15
  region: 1721.15,594.15 1721.15,791.78 1523.52,791.78 1523.52,594.15
  region: 2789.82,594.15 2789.82,791.78 2592.18,791.78 2592.18,594.15
Mechanical 3:
  pour cut-out: 1899.52,1.52 1899.52,520.2 2234.25,520.2 2234.25,1.52
Mechanical 15:
  lines w7.87: 4133.86,2664.92 4257.13,2664.92 ; 590.55,0 590.55,2637.8 4133.86,2637.8 4133.86,0 590.55,0
Mechanical 24:
  lines w3.94: 3414.61,2664.92 4257.13,2664.92
Mechanical 25:
  drawing of 1204 lines, arcs and shapes, not listed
